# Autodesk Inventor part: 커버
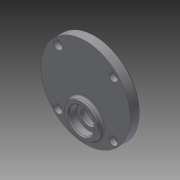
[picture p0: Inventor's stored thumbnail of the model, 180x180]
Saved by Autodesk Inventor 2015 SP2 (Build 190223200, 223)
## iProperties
Created: 2015-06
Part Number: 커버
Material: 일반
Document SubType Name: Modeling
Designer: AMC
Density: 1 g/cm^3
Appearance: 기본값
Author: AMC
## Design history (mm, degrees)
sketch "스케치1"
  geometry: C1 r 40 at (0, 0); 1 further point
  constraints: 1 centre point, 1 coincident
  dimensions: "d0" = 80 diameter of C1
extrude "돌출1" new body sketch "스케치1" distance "d1" = 9; taper "d2" = 0 deg
sketch "스케치2"
  geometry: C1 r 40 at (0, 0) reference; C2 r 15 at (0, -20); 2 further points
  constraints: 1 centre point, 1 coincident, 1 vertical alignment
  dimensions: "d4" = 30 diameter of C2; "d7" = 20 distance of C2.centre point (0, 0)
extrude "돌출2" join sketch "스케치2" distance "d5" = 4; taper "d6" = 0 deg
sketch "스케치3"
  geometry: C1 r 14 at (0, -11); C2 r 14 at (0, 20); 1 further point
  constraints: 2 centre point, 2 vertical alignment
  dimensions: "d8" = 28 diameter of C1; "d9" = 28 diameter of C2; "d10" = 20 distance of C2.centre point (0, 0); "d11" = 11 distance of point (0, 0) C1.centre
extrude "돌출3" join sketch "스케치3" distance "d12" = 3; taper "d13" = 0 deg
hole "구멍1" diameter "d16" = 15; stored, may be unused: countersink angle "d20" = 90 deg, drill point angle "d22" = 118 deg; dims "d14" = 10, "d15" = 10, "d17" = 6, "d18" = 22, "d19" = 7, "d21" = 8
hole "구멍2" diameter "d25" = 15; stored, may be unused: countersink angle "d29" = 90 deg, drill point angle "d31" = 118 deg; dims "d23" = 10, "d24" = 10, "d26" = 6, "d27" = 22, "d28" = 7, "d30" = 8
hole "구멍3" diameter "d34" = 18; stored, may be unused: countersink angle "d38" = 90 deg, drill point angle "d40" = 0 deg; dims "d35" = 6, "d36" = 22, "d37" = 7, "d39" = 8, "d41" = 10, "d42" = 10
sketch "스케치7"
  geometry: L1 (0, 0)-(0, 15.131); L2 (0, 0)-(24.749, 24.749); L3 (0, 0)-(35, 0); 1 further point
  constraints: 6 end point, 1 coincident, 1 equal length, 1 horizontal, 1 vertical
  dimensions: "d51" = 35 distance of L1.start L2.end; "d52" = 45 deg angle of L3 L2
hole "구멍4" sketch "스케치7" at (24.749, 24.749) diameter "d53" = 4.5; stored, may be unused: countersink angle "d57" = 90 deg, drill point angle "d59" = 0 deg; dims "d54" = 6, "d55" = 8, "d56" = 4.4, "d58" = 8
fillet "모깎기1" dims "d63" = 2
chamfer "모따기1" distance "d64" = 1; stored, may be unused: second distance "d65" = 2, angle "d66" = 45 deg
fillet "모깎기2" dims "d67" = 0.3
chamfer "모따기2" distance "d68" = 1; stored, may be unused: second distance "d69" = 2, angle "d70" = 45 deg
chamfer "모따기3" distance "d71" = 1; stored, may be unused: second distance "d72" = 2, angle "d73" = 45 deg
node "솔리드1"
pattern_circular "원형 패턴1" dims angle "d61" = 360 deg
